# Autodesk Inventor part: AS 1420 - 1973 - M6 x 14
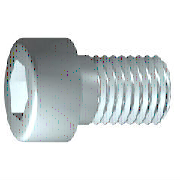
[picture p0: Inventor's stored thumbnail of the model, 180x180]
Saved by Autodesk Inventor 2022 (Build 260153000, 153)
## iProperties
Created: 2021-02
Part Number: AS 1420 - 1973 - M6 x 14
Material: Acciaio, Dolce
Description: Viti con esagono incassato metriche ISO
Document SubType Name: Modeling
Standard: AS 1420 - 1973
Designer: admin
Standards Organization: AS
Language: it-IT
Size Designation: M6 x 14
Categories: <MemberInstance><Categories><Category DisplayName="Elementi di fissaggio" InternalName="e4da775c-781d-43d5-af7c-5136215cf5a6" Mnemonic="FSTN"><Category DisplayN
Density: 7.85 g/cm^3
Appearance: Semilucidato
IsCustomPart: 0
Author: admin
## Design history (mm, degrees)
sketch "Schizzo1"
  geometry: L1 (-1.333, 0)-(14, 0); L2 (14, 0)-(14, 3); L3 (14, 3)-(2.5, 3); L4 (2.5, 3)-(1.886, 3); L5 (1.886, 3)-(0, 3); L6 (0, 3)-(0, 5); L7 (0, 5)-(-6, 5); L8 (-6, 5)-(-6, 2.887); L9 (-6, 2.887)-(-3, 2.887); L10 (-3, 2.887)-(-1.333, 0); L11 (-10, 0)-(18, 0) reference; L12 (0, -1)-(0, 6) reference; L13 (2.5, 3)-(0, 3)
  constraints: 22 end point, 6 parallel, 2 collinear, 2 perpendicular, 1 horizontal, 1 point on line
  dimensions: "d1" = 11.5 distance from line of L3.end L2 (= GEL); "d2" = 0.61355 distance of L4.end L3.end (computed from GAL); "d3" = 6 distance between parallel lines of L8 L6 (= KOH); "d4" = 3 distance of L8.end L9.end (= INTI); "d5" = 60 deg angle of L10 L1; "d6" = 6 diameter of L3 L1 (= GD); "d7" = 6 diameter of L5 L1 (= BDM); "d8" = 5.7735 diameter of L9 L1 (= 1.1547 x SW); "d9" = 10 diameter of L7 L1 (= KOD); "d26" = 14 distance between parallel lines of L12 L2 (= NLG)
revolve "Corpo" sketch "Schizzo1" stored, may be unused: angle "d10" = 90 deg
sketch "Schizzo2"
  geometry: L1 (0, -7)-(0, 7) reference; L2 (-7, 0)-(7, 0) reference; L3 (2.887, 0)-(1.443, -2.5); L4 (1.443, -2.5)-(-1.443, -2.5); L5 (-1.443, -2.5)-(-2.887, 0); L6 (-2.887, 0)-(-1.443, 2.5); L7 (-1.443, 2.5)-(1.443, 2.5); L8 (1.443, 2.5)-(2.887, 0); 2 further points
  constraints: 12 end point, 1 coincident, 1 horizontal alignment, 1 point on line, 12 other
extrude "Intaglio" join sketch "Schizzo2" stored distance "d11" = 10; taper "d12" = 0 deg
workplane "Work Plane1"
fillet "Fillet2" dims "d30" = 0.1 (= R)
body "Solid1"
fillet "Raccordo1" dims "d17" = 0.6 (= RR)
feature "Filettatura" dims "d13" = 11.5 (= GEL), "d14" = 0
chamfer "Smusso1" distance "d15" = 0.61345 (= -0.5 x SPD + 0.5 x GD); stored, may be unused: second distance "d16" = 0.61345 (= GUL), angle "d27" = 45 deg
other parameters: "GD" = 6 (= NND) [user parameter; used in 2 equation terms], "NLG" = 14 [user parameter; used in 1 equation term], "GEL" = 11.5 [user parameter; used in 2 equation terms], "KOD" = 10 [user parameter; used in 1 equation term], "KOH" = 6 (= NND) [user parameter; used in 1 equation term], "INTI" = 3 [user parameter; used in 1 equation term], "GAL" = 0.61345 (= 0.61345 x PTC) [user parameter; used in 1 equation term], "GUL" = 0.61345 (= 0.61345 x PTC) [user parameter; used in 1 equation term], "BDM" = 6 (= NND) [user parameter; used in 1 equation term], "SW" = 5 [user parameter; used in 2 equation terms], "RR" = 0.6 (= 0.1 x NND) [user parameter; used in 1 equation term], "SPD" = 4.7731 (= NND - 1.2269 x PTC) [user parameter; used in 1 equation term], "d19" = 0, "d28" = 0, "d29" = 0, "R" = 0.1 [user parameter; used in 1 equation term], "PHH" = 0.2 [user parameter], "GD1" = 4.7731 (= THREADDIA - 1.2269 x PTC) [user parameter], "THREADDIA" = 6 [user parameter; used in 1 equation term], "FAWI" = 45 deg [user parameter], "PTC" = 1 [user parameter; used in 5 equation terms], "KOH1" = 5.4 [user parameter], "NND" = 6 [user parameter; used in 5 equation terms], "TOA" = 30 deg [user parameter], "E0" = 5.775 (= 1.155 x SW) [user parameter]
